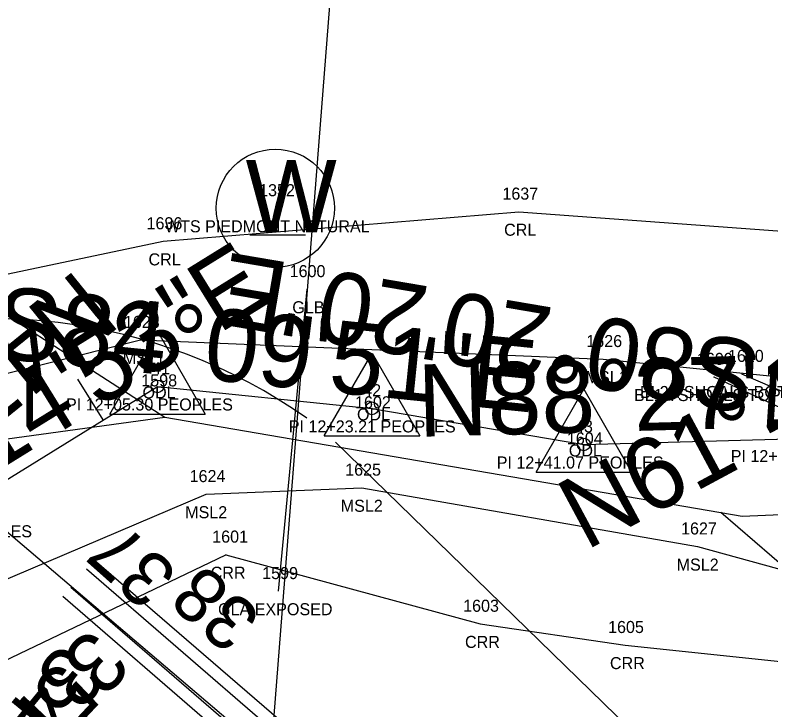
# Model space of a CAD drawing. Extents: x 1812113 to 1819860, y 1177395 to 1181185.
# Drawn here: x 1813790.4 to 1813853.2, y 1178707.7 to 1178765.4 of the extents above; entities that cross this region are included whole.
import ezdxf

# ---------------------------------------------------------------- set-up
doc = ezdxf.new("R2010")
doc.units = 0
for name, color, linetype in [('RD_DTM_BkLn1', 7, 'Continuous'), ('RD_EX_DV_Prop', 7, 'Continuous'), ('RD_EX_H2O', 7, 'Continuous'), ('RD_EX_H2O_txCode', 7, 'Continuous'), ('RD_EX_Misc', 7, 'Continuous'), ('RD_EX_Misc_txCode', 7, 'Continuous'), ('RD_EX_RW', 7, 'Continuous'), ('RD_EX_UT', 7, 'Continuous'), ('RD_EX_UT_txCode', 7, 'Continuous'), ('RD_HC_CL', 7, 'Continuous'), ('RD_HC_Data', 7, 'Continuous'), ('RD_HC_Data_Tic', 7, 'Continuous'), ('RD_HC_txCode', 7, 'Continuous'), ('RD_PD_ALT1_TnTmp', 7, 'Continuous'), ('RD_PD_ALT3_LnLine', 7, 'Continuous'), ('RD_PD_ALT4_LnLine', 7, 'Continuous'), ('RD_PD_BCA', 7, 'Continuous'), ('RD_PD_RW', 7, 'Continuous'), ('RD_SMD_Locator', 7, 'Continuous'), ('RD_SMD_Misc', 7, 'Continuous')]:
    doc.layers.add(name, color=color, linetype=linetype)

msp = doc.modelspace()

# ---------------------------------------------------------------- linework, layer by layer
at = {"layer": 'RD_DTM_BkLn1'}
for p, q in [((1813848.444, 1178735.384), (1813869.763, 1178725.59)), ((1813850.736, 1178735.637), (1813872.01, 1178726.486))]:
    msp.add_line(p, q, dxfattribs=at)
at = {"layer": 'RD_EX_DV_Prop'}
for p, q in [((1813850.785, 1178723.835), (1814093.607, 1178734.353)), ((1813781.836, 1178729.192), (1813802.812, 1178732.04)), ((1813802.812, 1178732.04), (1813850.785, 1178723.835)), ((1813854.673, 1178667.319), (1813781.836, 1178729.192))]:
    msp.add_line(p, q, dxfattribs=at)
at = {"layer": 'RD_EX_H2O'}
for points in [[(1813767.831, 1178739.336), (1813802.696, 1178746.648), (1813832.241, 1178749.109), (1813880.122, 1178745.593), (1813913.043, 1178737.891)], [(1813747.032, 1178677.406), (1813754.345, 1178684.796), (1813763.952, 1178688.126), (1813782.123, 1178708.315), (1813807.886, 1178720.632), (1813829.016, 1178714.89), (1813841.058, 1178713.127), (1813882.921, 1178708.729), (1813906.373, 1178716.286)]]:
    msp.add_lwpolyline(points, dxfattribs=at)
at = {"layer": 'RD_EX_Misc'}
for points in [[(1813573.261, 1178698.609), (1813581.176, 1178685.417), (1813588.271, 1178683.03), (1813621.867, 1178683.405), (1813652.093, 1178681.47), (1813685.623, 1178688.184), (1813723.849, 1178690.459), (1813735.911, 1178692.91), (1813768.219, 1178723.128), (1813784.539, 1178734.4), (1813800.789, 1178738.457), (1813839.236, 1178736.87), (1813863.895, 1178734.392), (1813884.494, 1178732.558), (1813903.275, 1178733.231)], [(1813591.145, 1178668.772), (1813628.984, 1178667.844), (1813655.761, 1178668.83), (1813686.954, 1178670.41), (1813726.51, 1178669.36), (1813738.941, 1178670.711), (1813788.676, 1178718.193), (1813806.253, 1178725.658), (1813819.179, 1178726.191), (1813847.084, 1178721.307), (1813860.38, 1178717.648), (1813871.967, 1178724.247), (1813883.921, 1178723.481), (1813902.674, 1178722.415)]]:
    msp.add_lwpolyline(points, dxfattribs=at)
at = {"layer": 'RD_EX_RW'}
msp.add_line((1813768.43, 1178754.211), (1813802.812, 1178732.04), dxfattribs=at)
at = {"layer": 'RD_EX_UT'}
for p, q in [((1813809.873, 1178747.186), (1813814.502, 1178747.186)), ((1813812.259, 1178717.603), (1813814.643, 1178742.673))]:
    msp.add_line(p, q, dxfattribs=at)
msp.add_lwpolyline([(1814122.48, 1178351.311), (1814099.725, 1178371.678), (1813807.047, 1178645.143), (1813817.449, 1178777.901), (1813883.812, 1178790.874)], dxfattribs=at)
msp.add_circle((1813812.001, 1178749.394), 4.908, dxfattribs=at)
at = {"layer": 'RD_HC_CL'}
for p, q in [((1813785.202, 1178724.075), (1813802.213, 1178734.602)), ((1813802.213, 1178734.602), (1813820.035, 1178732.781)), ((1813820.035, 1178732.781), (1813837.634, 1178729.785)), ((1813837.634, 1178729.785), (1813857.382, 1178730.318))]:
    msp.add_line(p, q, dxfattribs=at)
at = {"layer": 'RD_HC_Data'}
for p, q in [((1813798.242, 1178732.31), (1813802.214, 1178739.189)), ((1813802.214, 1178739.189), (1813806.183, 1178732.31)), ((1813816.064, 1178730.488), (1813820.036, 1178737.368)), ((1813820.036, 1178737.368), (1813824.004, 1178730.488)), ((1813833.664, 1178727.492), (1813837.636, 1178734.372)), ((1813837.636, 1178734.372), (1813841.604, 1178727.492)), ((1813798.242, 1178732.31), (1813806.183, 1178732.31)), ((1813816.064, 1178730.488), (1813824.004, 1178730.488)), ((1813833.664, 1178727.492), (1813841.604, 1178727.492))]:
    msp.add_line(p, q, dxfattribs=at)
for centre in [(1813802.213, 1178734.602), (1813820.035, 1178732.781), (1813837.634, 1178729.785)]:
    msp.add_circle(centre, 0.529, dxfattribs=at)
at = {"layer": 'RD_HC_Data_Tic'}
msp.add_line((1813797.707, 1178731.814), (1813795.602, 1178735.215), dxfattribs=at)
at = {"layer": 'RD_PD_ALT3_LnLine'}
for p, q in [((1813834.823, 1178687.519), (1813796.963, 1178720.177)), ((1813832.863, 1178685.247), (1813795.003, 1178717.906))]:
    msp.add_line(p, q, dxfattribs=at)
at = {"layer": 'RD_PD_ALT4_LnLine'}
for p, q in [((1813834.17, 1178686.761), (1813796.309, 1178719.42)), ((1813832.21, 1178684.49), (1813794.35, 1178717.149))]:
    msp.add_line(p, q, dxfattribs=at)
at = {"layer": 'RD_PD_BCA'}
msp.add_line((1813847.464, 1178700.339), (1813817.015, 1178729.964), dxfattribs=at)
msp.add_arc((1813788.637, 1178695.216), 45, 54.74185, 111.6999, dxfattribs=at)
at = {"layer": 'RD_PD_RW'}
msp.add_line((1813877.921, 1178699.206), (1813849.018, 1178724.137), dxfattribs=at)
at = {"layer": 'RD_SMD_Locator'}
for centre in [(1813832.241, 1178749.109), (1813802.696, 1178746.648), (1813814.643, 1178742.673), (1813800.789, 1178738.457), (1813839.236, 1178736.87), (1813848.444, 1178735.384), (1813850.736, 1178735.637), (1813802.213, 1178734.602), (1813802.213, 1178734.602), (1813820.035, 1178732.781), (1813820.035, 1178732.781), (1813837.634, 1178729.785), (1813837.634, 1178729.785), (1813819.179, 1178726.191), (1813806.253, 1178725.658), (1813847.084, 1178721.307), (1813807.886, 1178720.632), (1813812.259, 1178717.603), (1813829.016, 1178714.89), (1813841.058, 1178713.127)]:
    msp.add_circle(centre, 0.001, dxfattribs=at)

# ---------------------------------------------------------------- texts
at = {"layer": 'RD_EX_H2O_txCode'}
for s, p in [('1637', (1813830.87, 1178750.109)), ('1636', (1813801.303, 1178747.648)), ('CRL', (1813831.012, 1178747.109)), ('CRL', (1813801.468, 1178744.648)), ('1598', (1813800.867, 1178734.602)), ('ODL', (1813800.969, 1178733.602)), ('1602', (1813818.625, 1178732.781)), ('ODL', (1813818.79, 1178731.781)), ('1604', (1813836.225, 1178729.785)), ('ODL', (1813836.39, 1178728.785)), ('1601', (1813806.76, 1178721.632)), ('CRR', (1813806.634, 1178718.632)), ('1603', (1813827.607, 1178715.89)), ('1605', (1813839.649, 1178714.127)), ('CRR', (1813827.764, 1178712.89)), ('CRR', (1813839.806, 1178711.127))]:
    msp.add_text(s, height=1, dxfattribs=at).set_placement(p)
at = {"layer": 'RD_EX_Misc_txCode'}
for s, p in [('1623', (1813799.419, 1178739.457)), ('1626', (1813837.842, 1178737.87)), ('MSL1', (1813799.333, 1178736.457)), ('MSL1', (1813837.779, 1178734.87)), ('1624', (1813804.883, 1178726.658)), ('1625', (1813817.809, 1178727.191)), ('MSL2', (1813817.439, 1178724.191)), ('MSL2', (1813804.513, 1178723.658)), ('1627', (1813845.714, 1178722.307)), ('MSL2', (1813845.344, 1178719.307))]:
    msp.add_text(s, height=1, dxfattribs=at).set_placement(p)
at = {"layer": 'RD_EX_UT'}
msp.add_text('W', height=6, dxfattribs=at).set_placement((1813809.537, 1178747.393))
at = {"layer": 'RD_EX_UT_txCode'}
for s, p in [('1352', (1813810.655, 1178750.394)), ('WTS PIEDMONT NATURAL', (1813802.828, 1178747.394)), ('1600', (1813813.194, 1178743.673)), ('GLB', (1813813.414, 1178740.673)), ('1599', (1813810.912, 1178718.603)), ('GLA EXPOSED', (1813807.243, 1178715.603))]:
    msp.add_text(s, height=1, dxfattribs=at).set_placement(p)
at = {"layer": 'RD_HC_Data'}
msp.add_text('S80%%d20\'20"E', height=6, rotation=170.33888, dxfattribs=at).set_placement((1813852.508, 1178738.169))
at = {"layer": 'RD_HC_txCode'}
for s, p in [('41', (1813801.764, 1178735.602)), ('42', (1813819.302, 1178733.781)), ('PI 12+05.30 PEOPLES', (1813794.615, 1178732.602)), ('PI 12+23.21 PEOPLES', (1813813.121, 1178730.781)), ('43', (1813836.902, 1178730.785)), ('PI 12+60.82 PEOPLES', (1813849.838, 1178728.318)), ('PI 12+41.07 PEOPLES', (1813830.398, 1178727.785)), ('PI 11+85.30 PEOPLES', (1813777.927, 1178722.075))]:
    msp.add_text(s, height=1, dxfattribs=at).set_placement(p)
at = {"layer": 'RD_PD_ALT1_TnTmp'}
for s, rotation, p in [('N61%%d46\'05"E', 28.23186, (1813837.794, 1178720.936)), ('N58%%d14\'53"E', 31.75204, (1813773.138, 1178717.785)), ('N47%%d21\'19"E', 218.97815, (1813795.54, 1178744.441)), ('S84%%d09\'51"E', 354.16418, (1813788.509, 1178737.008)), ('N88%%d27\'11"E', 1.54697, (1813823.918, 1178730.415))]:
    msp.add_text(s, height=6, rotation=rotation, dxfattribs=at).set_placement(p)
at = {"layer": 'RD_PD_ALT3_LnLine'}
for s, height, rotation, p in [('38', 4.5, 138.8497, (1813811.007, 1178715.603)), ('35F', 5, 226.72337, (1813796.593, 1178714.722))]:
    msp.add_text(s, height=height, rotation=rotation, dxfattribs=at).set_placement(p)
at = {"layer": 'RD_PD_ALT4_LnLine'}
for s, height, rotation, p in [('37', 4.5, 138.34632, (1813804.082, 1178719.181)), ('34F', 5, 230.65202, (1813794.271, 1178713.486))]:
    msp.add_text(s, height=height, rotation=rotation, dxfattribs=at).set_placement(p)
at = {"layer": 'RD_SMD_Misc'}
for s, p in [('1610', (1813849.61, 1178736.637)), ('1609', (1813847.034, 1178736.384)), ('BL2A SHOALS BOTTOM', (1813842.303, 1178733.637)), ('BL1A SHOALS TOP', (1813841.806, 1178733.384))]:
    msp.add_text(s, height=1, dxfattribs=at).set_placement(p)

doc.saveas('drawing.dxf')
